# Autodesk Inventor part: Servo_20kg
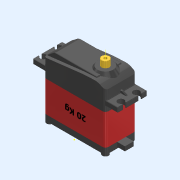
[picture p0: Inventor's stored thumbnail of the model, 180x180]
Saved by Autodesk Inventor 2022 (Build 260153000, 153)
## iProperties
Created: 2018-12
Part Number: Servo_20kg
Material: Generico
Document SubType Name: Modeling
Designer: admin
Density: 1 g/cm^3
Appearance: Default
Sending System: SolidWorks 2018
Last Author: admin
Last Saved: 2019-02-08
Author: admin
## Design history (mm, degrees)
feature "CirPattern1"
node "Asse di lavoro1"
sketch "Schizzo1"
  geometry: L1 (0, 0)-(16.1, 0) reference; L2 (5.59, 0)-(11.248, 0); L3 (11.248, 0)-(11.248, -2.81); L4 (11.248, -2.81)-(5.59, -2.81); L5 (5.59, -2.81)-(5.59, 0); 2 further points
  constraints: 8 end point, 2 parallel, 1 horizontal, 1 perpendicular, 1 point on line
extrude "Estrusione1" join sketch "Schizzo1" distance "d14" = 5; taper "d15" = 0 deg
node "Piano di lavoro1"
sketch "Schizzo2"
  geometry: L1 (25.629, 8.138)-(9.185, 8.138); L2 (9.185, 8.138)-(9.185, -9.288); L3 (9.185, -9.288)-(25.629, -9.288); L4 (25.629, -9.288)-(25.629, 8.138); 1 further point
  constraints: 2 other
node "Solido1"
other parameters: "d16" = 0
